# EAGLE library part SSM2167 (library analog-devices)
Low Voltage Microphone Preamplifier with Variable Compression and Noise Gating Source: http://www.analog.com .. SSM2167.pdf
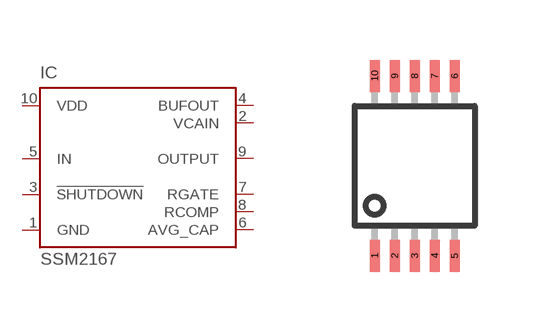
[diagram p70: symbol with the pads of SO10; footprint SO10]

Designator prefix IC

## SSM2167 (MPN: SSM2167Z-EVAL; OC_FARNELL: 1424672; OC_NEWARK: 65M4647)  [SO10]
1  GND  pwr
2  VCAIN  in
3  !SHUTDOWN  in
4  BUFOUT  out
5  IN  in
6  AVG_CAP  pas
7  RGATE  pas
8  RCOMP  pas
9  OUTPUT  out
10  VDD  pwr

## Footprint SO10 (pad centres in mm)
10-Lead Mini_SO Package (RM-10)
smd 0.25 x 0.8: 1 -1,-2.25; 2 -0.5,-2.25; 3 0,-2.25; 4 0.5,-2.25; 5 1,-2.25; 6 1,2.25; 7 0.5,2.25; 8 0,2.25; 9 -0.5,2.25; 10 -1,2.25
